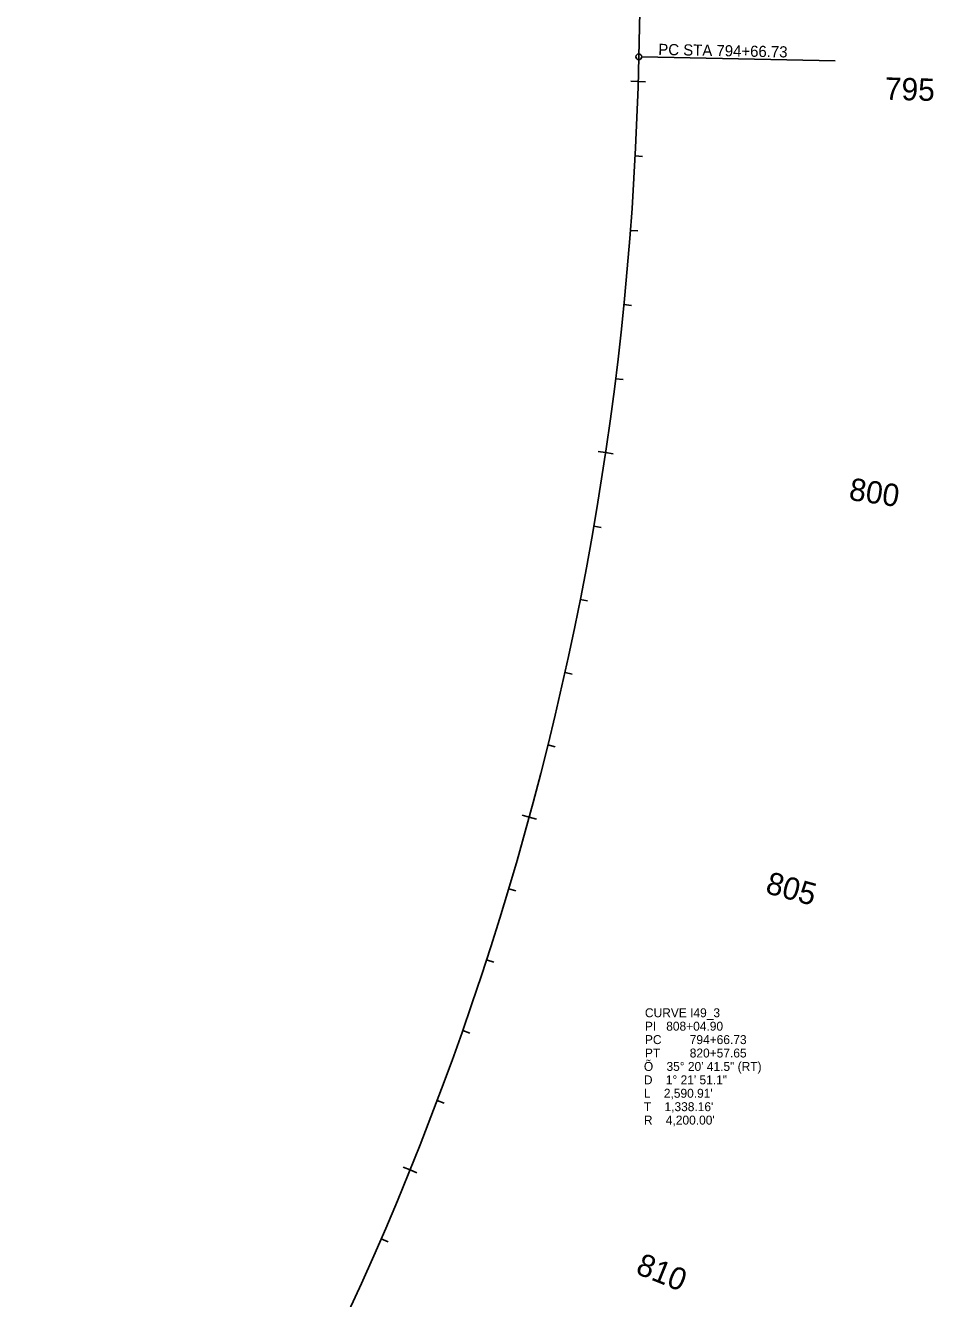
# Model space of a CAD drawing. Extents: x 2819977 to 2827606, y 116785 to 150320.
# Drawn here: x 2822878 to 2824096, y 137743 to 139451 of the extents above; entities that cross this region are included whole.
import ezdxf

# ---------------------------------------------------------------- set-up
doc = ezdxf.new("R2010")
doc.units = 0
for name, color, linetype in [('Default', 7, 'Continuous'), ('Modeling-Flow Arrows-Existing', 7, 'Continuous'), ('Modeling-Spot-Existing', 7, 'Continuous'), ('Modeling-Triangle Verticies-Existing', 7, 'Continuous')]:
    doc.layers.add(name, color=color, linetype=linetype)

msp = doc.modelspace()

# ---------------------------------------------------------------- linework, layer by layer
at = {"layer": 'Default'}
msp.add_arc((2819501.9, 139492.9), 4200, 323.5041, 358.849, dxfattribs=at)
at = {"layer": 'Modeling-Flow Arrows-Existing'}
for p, q in [((2823760.8, 142380.9), (2823701.1, 139408.5)), ((2823700.3, 139375.3), (2823690.3, 139375.6)), ((2823700.3, 139375.3), (2823710.2, 139375)), ((2823696.3, 139275.4), (2823706.2, 139274.9)), ((2823689.9, 139175.6), (2823699.9, 139174.8)), ((2823681.2, 139076), (2823691.1, 139075)), ((2823670, 138976.6), (2823680, 138975.4)), ((2823656.6, 138877.5), (2823646.7, 138879)), ((2823656.6, 138877.5), (2823666.5, 138876)), ((2823640.7, 138778.8), (2823650.6, 138777.1)), ((2823622.6, 138680.4), (2823632.4, 138678.5)), ((2823602.1, 138582.6), (2823611.8, 138580.4)), ((2823579.2, 138485.2), (2823588.9, 138482.8)), ((2823554.1, 138388.4), (2823544.4, 138391)), ((2823554.1, 138388.4), (2823563.7, 138385.8)), ((2823526.6, 138292.3), (2823536.2, 138289.4)), ((2823496.9, 138196.8), (2823506.4, 138193.7)), ((2823464.9, 138102), (2823474.3, 138098.7)), ((2823430.7, 138008.1), (2823440, 138004.5)), ((2823394.2, 137915), (2823384.9, 137918.7)), ((2823394.2, 137915), (2823403.5, 137911.2)), ((2823355.5, 137822.8), (2823364.7, 137818.8))]:
    msp.add_line(p, q, dxfattribs=at)
msp.add_arc((2819501.9, 139492.9), 4200, 323.5041, 358.849, dxfattribs=at)
at = {"layer": 'Modeling-Spot-Existing'}
msp.add_line((2823705.1, 139408.5), (2823964.7, 139403.2), dxfattribs=at)
msp.add_circle((2823701.1, 139408.5), 4, dxfattribs=at)

# ---------------------------------------------------------------- texts
at = {"layer": 'Modeling-Flow Arrows-Existing'}
for s, rotation, p in [(' 795', 358.3951, (2824019.7, 139351.3)), (' 800', 351.5742, (2823970.9, 138815.8)), (' 805', 344.7533, (2823858.9, 138289.8)), (' 810', 337.9324, (2823685.1, 137780.8))]:
    msp.add_text(s, height=30, rotation=rotation, dxfattribs=at).set_placement(p)
at = {"layer": 'Modeling-Spot-Existing'}
msp.add_text('PC STA 794+66.73', height=15, rotation=358.849, dxfattribs=at).set_placement((2823727.1, 139411))
at = {"layer": 'Modeling-Triangle Verticies-Existing'}
for s, p in [('CURVE I49_3', (2823709.3, 138119.9)), ('PI   808+04.90', (2823709.3, 138101.9)), ('PC', (2823709.3, 138083.9)), ('794+66.73', (2823769.4, 138083.9)), ('PT', (2823709.3, 138065.9)), ('820+57.65', (2823769.4, 138065.9)), ('Õ    35%%d 20\' 41.5" (RT)', (2823707.9, 138047.9)), ('D    1%%d 21\' 51.1"', (2823707.9, 138029.9)), ("L    2,590.91'", (2823707.9, 138011.9)), ("T    1,338.16'", (2823707.9, 137993.9)), ("R    4,200.00'", (2823707.9, 137975.9))]:
    msp.add_text(s, height=12, dxfattribs=at).set_placement(p)

doc.saveas('drawing.dxf')
